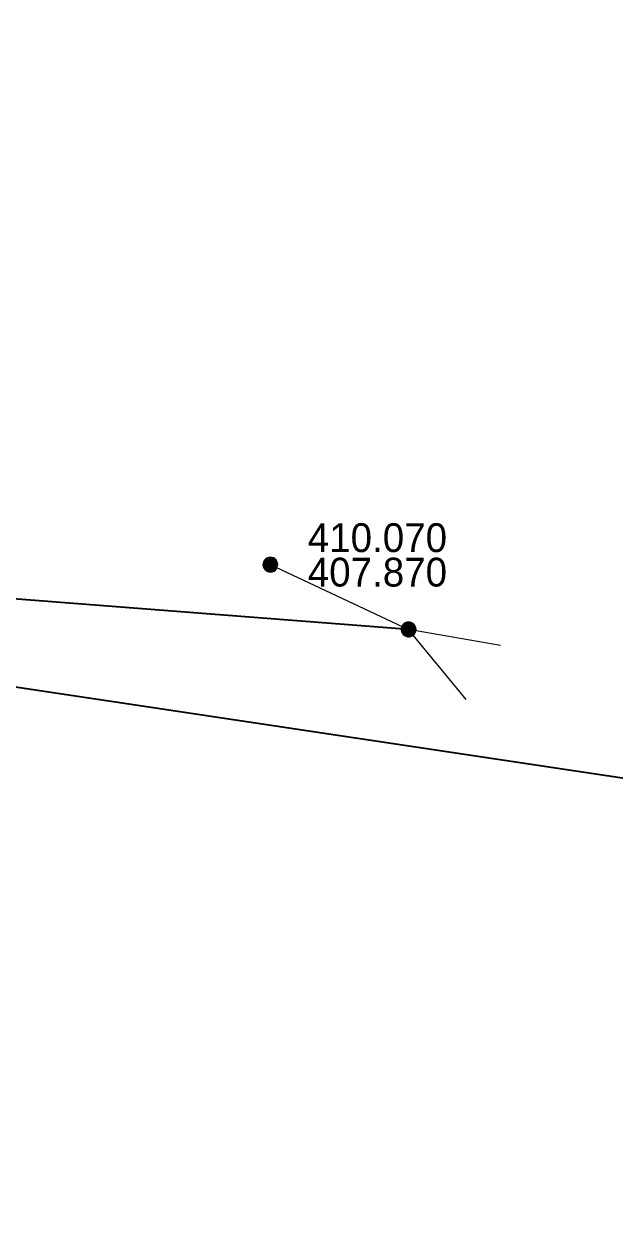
# Model space of a CAD drawing. Extents: x -867104 to -866746, y -1014489 to -1014255.
# Drawn here: x -866934.73 to -866916.28, y -1014426.06 to -1014388.58 of the extents above; entities that cross this region are included whole.
import ezdxf

# ---------------------------------------------------------------- set-up
doc = ezdxf.new("R2010")
doc.units = 0
doc.header["$LTSCALE"] = 0.44
for name, color, linetype, lineweight in [('1', 7, 'Continuous', 35), ('21', 7, 'Continuous', 35), ('23', 7, 'Continuous', 25), ('25', 7, 'Continuous', 13), ('32', 7, 'Continuous', 13)]:
    doc.layers.add(name, color=color, linetype=linetype, lineweight=lineweight)

msp = doc.modelspace()

# ---------------------------------------------------------------- linework, layer by layer
at = {"layer": '1'}
msp.add_lwpolyline([(-866877.679, -1014463.149), (-866884.593, -1014451.356), (-866912.586, -1014412.658), (-867006.516, -1014398.571), (-867098.057, -1014351.101)], dxfattribs=at)
at = {"layer": '21'}
msp.add_line((-866922.726, -1014407.49), (-866953.081, -1014405.138), dxfattribs=at)
at = {"layer": '23'}
for p in [(-866927.044, -1014405.466), (-866920.924, -1014409.674), (-866919.856, -1014407.992)]:
    msp.add_line(p, (-866922.726, -1014407.49), dxfattribs=at)
at = {"layer": '25'}
for points in [[(-866926.813, -1014405.466), (-866926.819, -1014405.414), (-866926.836, -1014405.364), (-866926.865, -1014405.32), (-866926.902, -1014405.283), (-866926.947, -1014405.256), (-866926.997, -1014405.239), (-866927.05, -1014405.235), (-866927.102, -1014405.242), (-866927.151, -1014405.261), (-866927.194, -1014405.29), (-866927.23, -1014405.329), (-866927.256, -1014405.374), (-866927.272, -1014405.425), (-866927.275, -1014405.477), (-866927.267, -1014405.529), (-866927.247, -1014405.578), (-866927.216, -1014405.621), (-866927.177, -1014405.655), (-866927.131, -1014405.681), (-866927.08, -1014405.695), (-866927.027, -1014405.697), (-866926.976, -1014405.687), (-866926.928, -1014405.666), (-866926.885, -1014405.635), (-866926.851, -1014405.594), (-866926.827, -1014405.548), (-866926.815, -1014405.497)], [(-866926.843, -1014405.466), (-866926.849, -1014405.417), (-866926.866, -1014405.371), (-866926.894, -1014405.331), (-866926.931, -1014405.299), (-866926.975, -1014405.277), (-866927.023, -1014405.266), (-866927.072, -1014405.266), (-866927.119, -1014405.279), (-866927.162, -1014405.303), (-866927.198, -1014405.336), (-866927.225, -1014405.377), (-866927.241, -1014405.424), (-866927.245, -1014405.473), (-866927.238, -1014405.521), (-866927.219, -1014405.566), (-866927.189, -1014405.606), (-866927.151, -1014405.637), (-866927.107, -1014405.657), (-866927.059, -1014405.667), (-866927.01, -1014405.665), (-866926.963, -1014405.65), (-866926.92, -1014405.625), (-866926.886, -1014405.591), (-866926.86, -1014405.549), (-866926.846, -1014405.502)], [(-866926.873, -1014405.466), (-866926.879, -1014405.421), (-866926.896, -1014405.379), (-866926.924, -1014405.344), (-866926.96, -1014405.317), (-866927.002, -1014405.3), (-866927.047, -1014405.295), (-866927.092, -1014405.301), (-866927.133, -1014405.32), (-866927.168, -1014405.348), (-866927.195, -1014405.385), (-866927.211, -1014405.427), (-866927.215, -1014405.472), (-866927.208, -1014405.517), (-866927.189, -1014405.558), (-866927.16, -1014405.592), (-866927.123, -1014405.618), (-866927.08, -1014405.634), (-866927.035, -1014405.637), (-866926.99, -1014405.629), (-866926.95, -1014405.609), (-866926.916, -1014405.58), (-866926.89, -1014405.542), (-866926.876, -1014405.499)], [(-866926.903, -1014405.466), (-866926.907, -1014405.425), (-866926.926, -1014405.388), (-866926.953, -1014405.357), (-866926.988, -1014405.336), (-866927.028, -1014405.325), (-866927.069, -1014405.327), (-866927.108, -1014405.34), (-866927.142, -1014405.364), (-866927.167, -1014405.396), (-866927.182, -1014405.434), (-866927.184, -1014405.475), (-866927.177, -1014405.515), (-866927.157, -1014405.551), (-866927.128, -1014405.58), (-866927.091, -1014405.599), (-866927.051, -1014405.607), (-866927.01, -1014405.603), (-866926.972, -1014405.588), (-866926.94, -1014405.562), (-866926.917, -1014405.528), (-866926.904, -1014405.489)], [(-866926.933, -1014405.466), (-866926.938, -1014405.43), (-866926.956, -1014405.398), (-866926.982, -1014405.373), (-866927.016, -1014405.358), (-866927.052, -1014405.355), (-866927.087, -1014405.363), (-866927.118, -1014405.383), (-866927.141, -1014405.411), (-866927.154, -1014405.445), (-866927.154, -1014405.482), (-866927.143, -1014405.517), (-866927.122, -1014405.546), (-866927.092, -1014405.567), (-866927.057, -1014405.577), (-866927.02, -1014405.575), (-866926.986, -1014405.561), (-866926.959, -1014405.538), (-866926.94, -1014405.506), (-866926.933, -1014405.471)], [(-866926.963, -1014405.466), (-866926.968, -1014405.435), (-866926.985, -1014405.409), (-866927.011, -1014405.392), (-866927.041, -1014405.385), (-866927.072, -1014405.389), (-866927.099, -1014405.406), (-866927.117, -1014405.43), (-866927.125, -1014405.461), (-866927.121, -1014405.491), (-866927.106, -1014405.519), (-866927.081, -1014405.538), (-866927.052, -1014405.547), (-866927.021, -1014405.544), (-866926.993, -1014405.53), (-866926.973, -1014405.506), (-866926.963, -1014405.477)], [(-866926.993, -1014405.466), (-866926.998, -1014405.442), (-866927.015, -1014405.424), (-866927.038, -1014405.415), (-866927.062, -1014405.418), (-866927.083, -1014405.432), (-866927.094, -1014405.454), (-866927.094, -1014405.479), (-866927.081, -1014405.5), (-866927.062, -1014405.514), (-866927.037, -1014405.517), (-866927.014, -1014405.508), (-866926.998, -1014405.49)], [(-866927.023, -1014405.466), (-866927.028, -1014405.451), (-866927.043, -1014405.445), (-866927.058, -1014405.449), (-866927.065, -1014405.463), (-866927.061, -1014405.478), (-866927.048, -1014405.487), (-866927.032, -1014405.484), (-866927.023, -1014405.472)]]:
    msp.add_lwpolyline(points, close=True, dxfattribs=at)
at = {"layer": '32'}
for points in [[(-866922.495, -1014407.49), (-866922.501, -1014407.438), (-866922.518, -1014407.388), (-866922.547, -1014407.344), (-866922.584, -1014407.307), (-866922.629, -1014407.28), (-866922.679, -1014407.263), (-866922.732, -1014407.259), (-866922.784, -1014407.266), (-866922.833, -1014407.285), (-866922.876, -1014407.314), (-866922.912, -1014407.353), (-866922.938, -1014407.398), (-866922.954, -1014407.449), (-866922.957, -1014407.501), (-866922.949, -1014407.553), (-866922.929, -1014407.602), (-866922.898, -1014407.645), (-866922.859, -1014407.679), (-866922.813, -1014407.705), (-866922.762, -1014407.719), (-866922.709, -1014407.721), (-866922.658, -1014407.711), (-866922.61, -1014407.69), (-866922.567, -1014407.659), (-866922.533, -1014407.618), (-866922.509, -1014407.572), (-866922.497, -1014407.521)], [(-866922.525, -1014407.49), (-866922.531, -1014407.441), (-866922.548, -1014407.395), (-866922.576, -1014407.355), (-866922.613, -1014407.323), (-866922.657, -1014407.301), (-866922.705, -1014407.29), (-866922.754, -1014407.29), (-866922.801, -1014407.303), (-866922.844, -1014407.327), (-866922.88, -1014407.36), (-866922.907, -1014407.401), (-866922.923, -1014407.448), (-866922.927, -1014407.497), (-866922.92, -1014407.545), (-866922.901, -1014407.59), (-866922.871, -1014407.63), (-866922.833, -1014407.661), (-866922.789, -1014407.681), (-866922.741, -1014407.691), (-866922.692, -1014407.689), (-866922.645, -1014407.674), (-866922.602, -1014407.649), (-866922.568, -1014407.615), (-866922.542, -1014407.573), (-866922.528, -1014407.526)], [(-866922.555, -1014407.49), (-866922.561, -1014407.445), (-866922.578, -1014407.403), (-866922.606, -1014407.368), (-866922.642, -1014407.341), (-866922.684, -1014407.324), (-866922.729, -1014407.319), (-866922.774, -1014407.325), (-866922.815, -1014407.344), (-866922.85, -1014407.372), (-866922.877, -1014407.409), (-866922.893, -1014407.451), (-866922.897, -1014407.496), (-866922.89, -1014407.541), (-866922.871, -1014407.582), (-866922.842, -1014407.616), (-866922.805, -1014407.642), (-866922.762, -1014407.658), (-866922.717, -1014407.661), (-866922.672, -1014407.653), (-866922.632, -1014407.633), (-866922.598, -1014407.604), (-866922.572, -1014407.566), (-866922.558, -1014407.523)], [(-866922.585, -1014407.49), (-866922.59, -1014407.449), (-866922.608, -1014407.412), (-866922.635, -1014407.381), (-866922.67, -1014407.36), (-866922.71, -1014407.349), (-866922.751, -1014407.351), (-866922.79, -1014407.364), (-866922.824, -1014407.388), (-866922.849, -1014407.42), (-866922.864, -1014407.458), (-866922.867, -1014407.499), (-866922.859, -1014407.539), (-866922.839, -1014407.575), (-866922.81, -1014407.604), (-866922.773, -1014407.623), (-866922.733, -1014407.631), (-866922.692, -1014407.627), (-866922.654, -1014407.612), (-866922.622, -1014407.586), (-866922.599, -1014407.552), (-866922.586, -1014407.513)], [(-866922.615, -1014407.49), (-866922.62, -1014407.454), (-866922.638, -1014407.422), (-866922.664, -1014407.397), (-866922.698, -1014407.382), (-866922.734, -1014407.379), (-866922.769, -1014407.387), (-866922.8, -1014407.407), (-866922.823, -1014407.435), (-866922.836, -1014407.469), (-866922.836, -1014407.506), (-866922.825, -1014407.541), (-866922.804, -1014407.57), (-866922.774, -1014407.591), (-866922.739, -1014407.601), (-866922.702, -1014407.599), (-866922.668, -1014407.585), (-866922.641, -1014407.562), (-866922.622, -1014407.53), (-866922.615, -1014407.495)], [(-866922.645, -1014407.49), (-866922.65, -1014407.459), (-866922.667, -1014407.433), (-866922.693, -1014407.416), (-866922.723, -1014407.409), (-866922.754, -1014407.413), (-866922.781, -1014407.43), (-866922.799, -1014407.454), (-866922.807, -1014407.485), (-866922.803, -1014407.515), (-866922.788, -1014407.543), (-866922.764, -1014407.562), (-866922.734, -1014407.571), (-866922.703, -1014407.568), (-866922.675, -1014407.554), (-866922.655, -1014407.53), (-866922.645, -1014407.501)], [(-866922.675, -1014407.49), (-866922.68, -1014407.466), (-866922.697, -1014407.448), (-866922.72, -1014407.439), (-866922.744, -1014407.442), (-866922.765, -1014407.456), (-866922.776, -1014407.478), (-866922.776, -1014407.503), (-866922.764, -1014407.524), (-866922.744, -1014407.538), (-866922.719, -1014407.541), (-866922.696, -1014407.532), (-866922.68, -1014407.514)], [(-866922.705, -1014407.49), (-866922.71, -1014407.475), (-866922.725, -1014407.469), (-866922.74, -1014407.473), (-866922.747, -1014407.487), (-866922.743, -1014407.502), (-866922.73, -1014407.511), (-866922.715, -1014407.508), (-866922.705, -1014407.496)]]:
    msp.add_lwpolyline(points, close=True, dxfattribs=at)

# ---------------------------------------------------------------- texts
at = {"layer": '1'}
for s, p in [('410.070 ', (-866925.875, -1014405.073)), ('407.870 ', (-866925.875, -1014406.15))]:
    msp.add_text(s, height=0.9, dxfattribs=at).set_placement(p)

doc.saveas('drawing.dxf')
